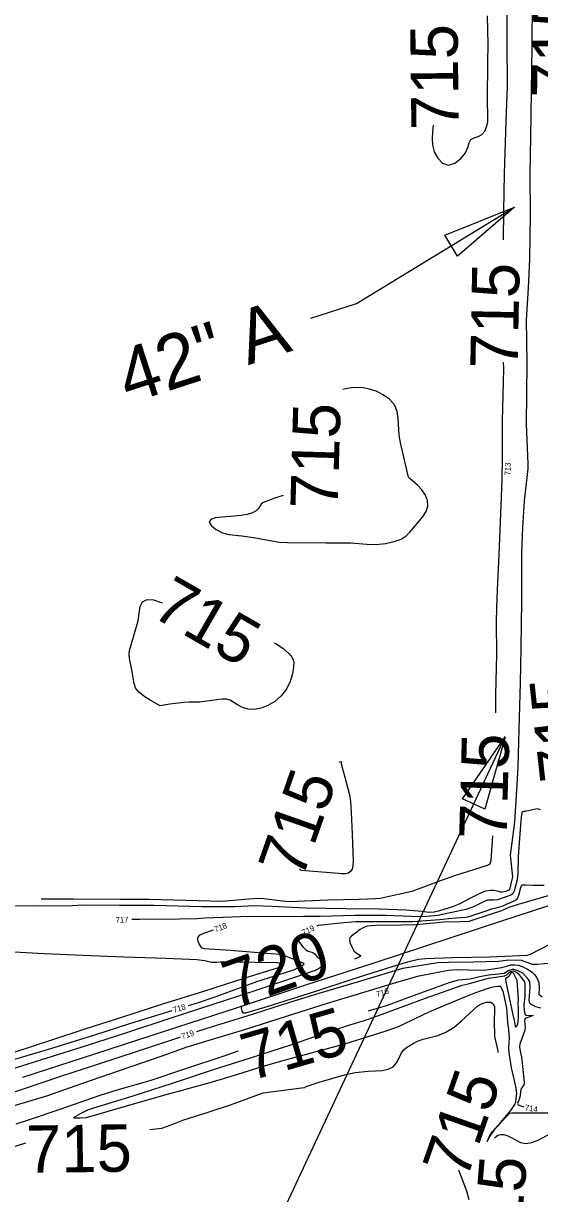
# Model space of a CAD drawing. Extents: x -468563856 to 36492962, y -306094093 to 11899197.
# Drawn here: x 1821405 to 1821764, y 530800 to 531615 of the extents above; entities that cross this region are included whole.
import ezdxf

# ---------------------------------------------------------------- set-up
doc = ezdxf.new("R2010")
doc.units = 0
for name, color, linetype in [('DT_X_Contour_Minor', 7, 'Continuous'), ('Level 14', 7, 'Continuous'), ('Level 19', 7, 'Continuous'), ('Level 40', 7, 'Continuous')]:
    doc.layers.add(name, color=color, linetype=linetype)

msp = doc.modelspace()

# ---------------------------------------------------------------- linework, layer by layer
at = {"layer": 'DT_X_Contour_Minor'}
for points in [[(1821388.03, 531000.73), (1821414.14, 531000.46), (1821438.84, 531000.74), (1821446.91, 531001.12), (1821471.57, 531001.1), (1821495.84, 531000.91), (1821528.89, 531000.07), (1821552.25, 530999.97), (1821565.46, 531000.79), (1821577.63, 531000.28), (1821601.34, 530999.03), (1821629.18, 530998.59), (1821652.32, 530998.42), (1821671.31, 530997.85), (1821682.44, 530996.77), (1821687.06, 530996.24), (1821690.73, 530996.39), (1821694.72, 530997.19), (1821704.38, 531000.36), (1821708.86, 531002.17), (1821716.6, 531006.24), (1821723.57, 531009.77), (1821726.71, 531010.86), (1821730.18, 531011.42), (1821732.15, 531011.43), (1821734.23, 531011.03), (1821736.8, 531010.2), (1821737.85, 531010.19), (1821740.72, 531010.85), (1821743.39, 531011.79), (1821745.56, 531020.63), (1821743.96, 531035.89), (1821746.8, 531058.75), (1821748.58, 531084.95), (1821749.12, 531097.03), (1821749.87, 531123.36), (1821750.84, 531155.7), (1821751.34, 531179.74), (1821751.76, 531212.69), (1821751.79, 531246.08), (1821752.49, 531263.83), (1821753.61, 531282.32), (1821755.13, 531296.61), (1821756.07, 531304.79), (1821756.14, 531307.91), (1821755.01, 531335.94), (1821755.13, 531356.71), (1821755.45, 531377.87), (1821755.06, 531408.36), (1821756.42, 531430.43), (1821757.25, 531450.55), (1821757.66, 531481.76), (1821757.58, 531509.72), (1821757.95, 531535.57), (1821758.5, 531567.06), (1821758.87, 531598.66), (1821759.23, 531630.84)], [(1821741.4, 531622.8), (1821741.18, 531602.32), (1821741.43, 531570.87), (1821740.66, 531546.47), (1821739.49, 531509.88), (1821738.91, 531484.16), (1821738.72, 531464.06)], [(1821690.01, 531543.78), (1821689.58, 531538.85), (1821689.38, 531534.49), (1821689.65, 531529.87), (1821690.81, 531525.17), (1821693.16, 531520.7), (1821696.55, 531517.32), (1821700.66, 531515.98), (1821705.15, 531517.29), (1821709.35, 531520.51), (1821712.51, 531524.5), (1821714.21, 531528.3), (1821715.15, 531531.49), (1821716.33, 531533.77), (1821718.49, 531535.04), (1821721.23, 531535.93), (1821723.88, 531537.24), (1821725.91, 531539.55), (1821727.24, 531542.56), (1821727.96, 531545.75), (1821728.15, 531548.79), (1821727.75, 531561.65), (1821728.14, 531587.49), (1821728.23, 531600.07), (1821727.94, 531619.84)], [(1821738.73, 531378.92), (1821738.93, 531374.69), (1821738.83, 531364.91), (1821738.01, 531338.1), (1821737.96, 531312.42), (1821737.74, 531297.08), (1821736.86, 531273.5), (1821735.81, 531244.88), (1821734.52, 531220.54), (1821734.01, 531208.13), (1821733.98, 531197.66), (1821734.14, 531175.73), (1821733.51, 531147.08), (1821733.42, 531134.72)], [(1821585.64, 531286.09), (1821579.66, 531284.23), (1821575.01, 531282.45), (1821572.89, 531281.73), (1821571.48, 531281.03), (1821570.23, 531279.99), (1821568.46, 531276.96), (1821566.88, 531275.37), (1821564.2, 531274), (1821560.57, 531272.93), (1821556.34, 531272.21), (1821538.34, 531270.63), (1821535.26, 531269.43), (1821534.18, 531267.57), (1821535.67, 531265.02), (1821539.07, 531262.33), (1821543.39, 531260.13), (1821547.85, 531258.9), (1821556.94, 531257.99), (1821566.26, 531256.72), (1821582.92, 531253.57), (1821588.63, 531253.35), (1821615.31, 531253.24), (1821632.67, 531253.08), (1821643.87, 531252.16), (1821650.36, 531252.08), (1821656.87, 531252.7), (1821662.84, 531253.96), (1821667.7, 531255.73), (1821671.12, 531257.91), (1821673.69, 531260.51), (1821682.62, 531270.93), (1821685.13, 531274.87), (1821686.3, 531278.75), (1821686.1, 531282.56), (1821684.64, 531286.3), (1821682.13, 531289.94), (1821679.19, 531293.17), (1821673.87, 531297.85), (1821672.95, 531298.91), (1821671.89, 531302.74), (1821667.33, 531322.83), (1821666.42, 531328.3), (1821665.81, 531335.42), (1821665.58, 531339.86), (1821664.85, 531344.56), (1821663.02, 531349.06), (1821659.66, 531352.99), (1821655.23, 531356.2), (1821650.42, 531358.61), (1821645.76, 531360.17), (1821641.34, 531360.98), (1821637.09, 531361.17), (1821633.02, 531360.9), (1821629.22, 531360.28), (1821627.12, 531359.72)], [(1821579.12, 531183.64), (1821580.61, 531183.05), (1821585.65, 531179.71), (1821589.56, 531176.23), (1821591.93, 531173.27), (1821592.93, 531170.38), (1821592.9, 531166.81), (1821592.09, 531162.05), (1821590.44, 531156.6), (1821587.81, 531151.24), (1821584.16, 531146.57), (1821579.77, 531142.78), (1821575.01, 531139.9), (1821570.21, 531137.98), (1821565.56, 531137.08), (1821561.19, 531137.27), (1821557.26, 531138.52), (1821553.84, 531140.36), (1821548.72, 531143.59), (1821546.28, 531144.36), (1821542.87, 531144.43), (1821532.42, 531142.98), (1821527.25, 531142.3), (1821519.85, 531142.2), (1821516.14, 531142.14), (1821506.81, 531140.92), (1821500.01, 531139.71), (1821493.11, 531143.63), (1821488.6, 531146.48), (1821484.81, 531149.47), (1821482.72, 531152.28), (1821481.85, 531155.25), (1821480.45, 531163.52), (1821478.61, 531172.62), (1821478.31, 531175.59), (1821478.64, 531178.17), (1821484.56, 531198.9), (1821486.15, 531209.05), (1821487.78, 531212.18), (1821490.93, 531213.62), (1821495.39, 531213.43), (1821500.78, 531211.69), (1821501.48, 531211.33)], [(1821624.55, 531100.61), (1821625.69, 531101), (1821626.1, 531100.67), (1821626.09, 531099.63), (1821626.28, 531098.36), (1821628.49, 531090.13), (1821631.76, 531077.76), (1821632.56, 531073.19), (1821632.92, 531065.69), (1821633.58, 531050.29), (1821634.39, 531031.65), (1821634.2, 531028.52), (1821633.59, 531026.1), (1821632.46, 531024.39), (1821630.93, 531023.31), (1821629.23, 531022.75), (1821626.03, 531022.69), (1821624.06, 531023), (1821598.2, 531025.11), (1821597.61, 531025.46), (1821597.3, 531026.21)], [(1821764.82, 531067.31), (1821762.32, 531067.94), (1821754.4, 531066.18), (1821752.95, 531066.15), (1821752.02, 531065.71), (1821751.46, 531064.41), (1821750.94, 531059.88), (1821749.1, 531034.83), (1821748.95, 531022.52), (1821748.16, 531017.72), (1821746.31, 531010.79), (1821745.46, 531008.92), (1821744.02, 531007.94), (1821734.79, 531004.82), (1821731.94, 531004.54), (1821727.68, 531004.5), (1821724.99, 531003.3), (1821718.05, 530999.95), (1821712.66, 530997.97), (1821693.18, 530993.78), (1821682.94, 530992.85), (1821674.88, 530993), (1821657.39, 530993.71), (1821635.62, 530993.92), (1821611.31, 530993.14), (1821599.8, 530993.19), (1821577.98, 530992.99), (1821573.8, 530993.12), (1821556.14, 530992.85), (1821531.03, 530991.97), (1821525.52, 530991.59), (1821513.51, 530991.3), (1821485.66, 530991.04), (1821480.23, 530990.94)], [(1821731.29, 531049.35), (1821730.07, 531032.1), (1821729.39, 531029.43), (1821727.72, 531028.6), (1821704.86, 531021.39), (1821697.06, 531018.66), (1821675.1, 531010.52), (1821653.12, 531005.67), (1821649.85, 531005.36), (1821638.2, 531004.98), (1821616.65, 531004.41), (1821589.93, 531003.22), (1821584.9, 531003.68), (1821572.11, 531005.38), (1821568.38, 531005.55), (1821561.62, 531005.17), (1821542.8, 531003.56), (1821526.53, 531004.06), (1821492.08, 531004.95), (1821472.54, 531004.95), (1821439.67, 531005.16), (1821417.17, 531005.06)], [(1821767.21, 531014.59), (1821759.94, 531014.74), (1821754.18, 531014.81), (1821751.81, 531014.86), (1821751.31, 531014.48), (1821750.87, 531012.97), (1821749.41, 531007.68), (1821748.66, 531005.91), (1821747.82, 531004.76), (1821745.61, 531003.54), (1821740.77, 531001.41), (1821737.7, 531000.02), (1821734.62, 530999.09), (1821730.73, 530998.2), (1821725.25, 530996.47), (1821716.31, 530993.26), (1821713.09, 530992.52), (1821706.1, 530991.96), (1821700.7, 530991.56), (1821694.61, 530990.76), (1821675.57, 530989.44), (1821671.96, 530989.37), (1821658.25, 530989.51), (1821635.99, 530989.39), (1821625.42, 530988.48), (1821610.06, 530986.84), (1821609.11, 530986.5)], [(1821772.38, 531008.25), (1821749.21, 531001.46), (1821742.69, 530999.26), (1821737.48, 530997.03), (1821735.44, 530996.26), (1821731.86, 530995.19), (1821714.81, 530989.63), (1821708.86, 530989.33), (1821697.44, 530989.2), (1821690.45, 530988.58), (1821678.27, 530987.3), (1821667.93, 530987.07), (1821649.85, 530986.92), (1821646.76, 530986.73), (1821644.12, 530986.29), (1821641.68, 530985.44), (1821639.25, 530984.07), (1821633.22, 530979.52), (1821632.11, 530978.28), (1821631.68, 530976.86), (1821631.97, 530975.09), (1821633.58, 530971.47), (1821634.89, 530969.25), (1821636.35, 530967.82), (1821639.34, 530966.05), (1821639.11, 530965.24), (1821636.44, 530963.84), (1821635.25, 530963.43)], [(1821556.93, 530931.18), (1821556.34, 530929.44), (1821556.77, 530927.2), (1821557.46, 530926.02), (1821559.59, 530926.08), (1821574.45, 530930.55), (1821608.44, 530941.22), (1821633.7, 530949.47), (1821661.44, 530958.4), (1821673.02, 530961.83), (1821679.91, 530963.4), (1821684.7, 530963.89), (1821703.51, 530964.55), (1821729.33, 530965.12), (1821755.5, 530966.09), (1821757.73, 530967.01), (1821771.63, 530974.15), (1821773.55, 530975.78), (1821774.46, 530977.69), (1821775.14, 530982.55), (1821776.5, 530985.4), (1821777, 530986.98), (1821776.97, 530989.17), (1821776.97, 530989.24)], [(1821598.48, 530980.92), (1821597.11, 530980.08), (1821596.07, 530978.87), (1821595.93, 530977.51), (1821596.62, 530975.8), (1821599.12, 530972.26), (1821601.15, 530970.07), (1821603.11, 530969.05), (1821606.34, 530967.97), (1821607.88, 530966.95), (1821609.32, 530965.16), (1821611.87, 530962.82), (1821612.85, 530961.42), (1821613.08, 530960.02), (1821612.62, 530958.7), (1821611.64, 530957.55), (1821610.23, 530956.61), (1821607.96, 530955.63), (1821592.8, 530950.44), (1821564.4, 530940.99), (1821536.01, 530931.66), (1821506.6, 530922.07), (1821477.15, 530912.37), (1821449.2, 530903.38), (1821421.18, 530894.46), (1821390.9, 530884.92)], [(1821519.75, 530931.18), (1821525.88, 530933), (1821538.2, 530937.17), (1821567.32, 530947.92), (1821593.07, 530956.08), (1821598.11, 530958.47), (1821600.23, 530959.82), (1821599.91, 530960.31), (1821594.91, 530962.52), (1821584.49, 530966.61), (1821576.77, 530967.09), (1821549.01, 530969.47), (1821530.82, 530970.62), (1821529.18, 530971.15), (1821528.28, 530972.25), (1821527.16, 530974.13), (1821526.24, 530976.43), (1821526.27, 530978.6), (1821527.78, 530980.27), (1821530.4, 530981.51), (1821537.13, 530983.83)], [(1821389.97, 530969.09), (1821419.18, 530967.44), (1821446.38, 530966.11), (1821474.63, 530965.13), (1821504.1, 530964.1), (1821525.48, 530963.28), (1821531.19, 530962.38), (1821535.72, 530961.42), (1821539.52, 530961.38), (1821541.81, 530961.63), (1821557.41, 530961.59), (1821574.35, 530961.2), (1821580.23, 530961.27), (1821583.7, 530960.65), (1821585.73, 530959.61), (1821585.75, 530959.19), (1821584.62, 530958.54), (1821582.15, 530957.5), (1821558.96, 530950.14), (1821530.04, 530940.88), (1821501.71, 530932.02), (1821472.96, 530922.85), (1821448.26, 530915.06), (1821424.26, 530907.13), (1821398.74, 530898.66)], [(1821525.61, 530913.05), (1821536.33, 530916.51), (1821560.44, 530924.1), (1821589.51, 530933.21), (1821610.74, 530939.68), (1821641.28, 530948.87), (1821668.96, 530957.14), (1821687.52, 530960.17), (1821693.34, 530961.03), (1821700.64, 530961.39), (1821718.09, 530961.61), (1821735.5, 530962.14), (1821740.94, 530962.65), (1821742.65, 530963), (1821751.36, 530962.68), (1821753.21, 530962.09), (1821759.1, 530959.83), (1821762.67, 530960), (1821777.19, 530961.33), (1821778.48, 530961.47)], [(1821771.63, 530856.23), (1821744.83, 530856.35), (1821743.17, 530855.93), (1821740.18, 530852.9), (1821732.08, 530843.89), (1821729.42, 530840.2), (1821727.62, 530836.54), (1821729.73, 530841.18), (1821731.36, 530843.57), (1821737.25, 530850.31), (1821744.09, 530858.22), (1821746.91, 530862.36), (1821747.67, 530864.05), (1821747.84, 530866.41), (1821748.2, 530869.92), (1821747.89, 530873.43), (1821746.67, 530879.01), (1821744.61, 530887.81), (1821742.88, 530898.48), (1821742.73, 530901.43), (1821743.19, 530908.81), (1821742.69, 530914.05), (1821742.04, 530919.91), (1821741.27, 530929.32), (1821738.89, 530940.16), (1821737.36, 530943.87), (1821736.83, 530944.3), (1821735.11, 530944.46), (1821731.65, 530943.84), (1821728.06, 530942.95), (1821719.44, 530939.96), (1821712.62, 530937.17), (1821699.18, 530931.59), (1821687.57, 530926.77), (1821665.73, 530916.31), (1821656.45, 530913.09), (1821628.21, 530904.36), (1821610.28, 530899.38), (1821584.4, 530892.56), (1821570.78, 530888.55), (1821553.81, 530883.27), (1821534.64, 530877.46), (1821504.88, 530869.27), (1821482.75, 530862.93), (1821448.47, 530853.01), (1821444.21, 530852.74), (1821440.25, 530852.7), (1821439.67, 530852.95), (1821440.11, 530853.43), (1821444.97, 530856.31), (1821449.74, 530858.58), (1821453.77, 530859.9), (1821481.14, 530868.43), (1821508.53, 530877.09), (1821537.2, 530886.55), (1821562.83, 530894.76), (1821591.57, 530903.98), (1821613.71, 530911.66), (1821632.03, 530917.67), (1821642.27, 530920.73), (1821654.53, 530925.11), (1821684.73, 530936.3), (1821710.1, 530945.4), (1821714.38, 530946.21), (1821728.42, 530950.19), (1821735.06, 530951.18), (1821739.68, 530951.86), (1821741.25, 530952.47), (1821741.97, 530953.26), (1821742.81, 530954.19), (1821744.21, 530954.99), (1821745.68, 530955.19), (1821747.53, 530954.58), (1821749.26, 530953.5), (1821749.98, 530952.46), (1821751.32, 530950.6), (1821753.68, 530947.54), (1821753.88, 530945.81), (1821753.82, 530937.38), (1821753.1, 530931.72), (1821753.45, 530927.36), (1821754.01, 530924.86), (1821754.5, 530924.52), (1821759.53, 530924.27), (1821754.14, 530922.06), (1821753.67, 530921.07), (1821753.84, 530918.18), (1821753.98, 530916.22), (1821753.76, 530913.94), (1821752.99, 530911.38), (1821750.36, 530904.2), (1821750.13, 530902.44)], [(1821472.3, 530886.16), (1821501.34, 530896.27), (1821518.74, 530902.36), (1821536.41, 530907.77), (1821559.55, 530914.72), (1821588, 530923.71), (1821616.46, 530932.78), (1821645.76, 530941.65), (1821664.8, 530947.5), (1821680.31, 530951.73), (1821689.75, 530953.71), (1821700.68, 530955.76), (1821705.93, 530956.24), (1821714.63, 530956.02), (1821724.99, 530955.88), (1821730.27, 530956.39), (1821737.71, 530957.61), (1821741.15, 530958.55), (1821743.89, 530959.48), (1821746.81, 530959.59), (1821749.11, 530959.31), (1821752.45, 530958.03), (1821755.79, 530956.48), (1821758.94, 530954.33), (1821760.46, 530952.78), (1821762.07, 530950.47), (1821762.88, 530948.9), (1821763.47, 530947.09), (1821763.69, 530943.26), (1821763.49, 530939.01), (1821765.91, 530937.15)], [(1821764.98, 530929.42), (1821761.56, 530930.34), (1821758.16, 530931.77), (1821757.48, 530932.34), (1821757.02, 530933.4), (1821756.95, 530935.06), (1821757.56, 530943.39), (1821757.33, 530947.79), (1821756.3, 530949.22), (1821752.35, 530953.67), (1821749.02, 530955.41), (1821746.17, 530956.34), (1821745.01, 530956.33), (1821742.79, 530955.51), (1821739.42, 530953.53), (1821728.66, 530952.21), (1821722.23, 530951.11), (1821715.77, 530949.6), (1821707.72, 530948.85), (1821701.62, 530947.11), (1821681.31, 530939.72), (1821657.24, 530931.06), (1821644.87, 530927.3)], [(1821740.31, 530948.72), (1821745.54, 530924.75), (1821746.52, 530919.86), (1821747.16, 530916.6), (1821747.56, 530916.15), (1821748.06, 530916.46), (1821748.93, 530918.2), (1821749.07, 530919.83), (1821749.35, 530923.46), (1821749.39, 530929.2), (1821749.27, 530932.89), (1821749.38, 530935.46), (1821748.46, 530948.57), (1821746.05, 530953.74), (1821744.84, 530954.03), (1821744.17, 530953.77), (1821743.6, 530953.07), (1821742.78, 530951.32), (1821740.45, 530949.75), (1821740.31, 530948.72)], [(1821492.9, 530844.86), (1821501.11, 530845.76), (1821507.64, 530848.25), (1821515.76, 530851.33), (1821534.14, 530857.12), (1821548.99, 530862.09), (1821571.73, 530870.42), (1821598.27, 530873.9), (1821600.79, 530874.23), (1821601.1, 530874.47), (1821602.27, 530875.03), (1821610.6, 530877.81), (1821628.21, 530882.97), (1821635.78, 530884.48), (1821644.84, 530885.39), (1821654.44, 530886.03), (1821658.67, 530886.78), (1821662.13, 530888.49), (1821664.64, 530891.44), (1821668.06, 530898.17), (1821669.71, 530900.39), (1821671.56, 530901.89), (1821676.16, 530904.7), (1821679.2, 530906.28), (1821683.03, 530907.7), (1821693.19, 530910.3), (1821698.9, 530912.62), (1821704.57, 530916.21), (1821709.85, 530920.52), (1821721.19, 530930.92), (1821724.11, 530932.66), (1821727.14, 530933.49), (1821729.9, 530933.39), (1821731.87, 530932.31), (1821732.69, 530930.27), (1821732.72, 530927.49), (1821732.44, 530920.84), (1821732.74, 530909.69), (1821734.95, 530899.53), (1821735.03, 530898.48)], [(1821392.62, 530892), (1821423.93, 530901.3), (1821454.46, 530910.83), (1821478.96, 530918.63), (1821506.03, 530927.1), (1821508.25, 530927.76)], [(1821251.22, 530820.8), (1821263.56, 530824.25), (1821265.44, 530824.75), (1821277.23, 530829.55), (1821294.11, 530835.98), (1821306.1, 530840.14), (1821334.35, 530849.22), (1821354.52, 530856.11), (1821381.43, 530865.42), (1821404.23, 530873.06), (1821430.88, 530882.06), (1821456.62, 530890.46), (1821484.17, 530899.5), (1821512.94, 530908.96), (1821514.19, 530909.36)], [(1821554.36, 530899.34), (1821544.38, 530895.98), (1821516.24, 530886.7), (1821492.78, 530878.74), (1821482.04, 530875.71), (1821471.34, 530872.74), (1821457.97, 530868.47), (1821430.24, 530858.74), (1821408.71, 530851.67), (1821399.56, 530848.65)], [(1821750.13, 530902.44), (1821750.51, 530899.5), (1821751.54, 530895.25), (1821753.17, 530880.3), (1821753.41, 530877.35), (1821753.18, 530876.07), (1821751.93, 530874.24), (1821751.32, 530873.39), (1821750.84, 530871.27), (1821750.54, 530868.28), (1821749.61, 530865.26), (1821748.62, 530863.05), (1821749.26, 530862.11), (1821751.82, 530861.02), (1821753.18, 530860.69)], [(1821393.07, 530860.01), (1821421.74, 530868.63), (1821444.68, 530876.69), (1821472.3, 530886.16)], [(1821732.67, 530838.9), (1821733.58, 530839.89), (1821734.94, 530840.87), (1821736.82, 530841.48), (1821739.21, 530841.37), (1821741.95, 530840.56), (1821744.85, 530839.18), (1821747.75, 530837.42), (1821750.87, 530835.87), (1821754.45, 530835.21), (1821758.69, 530835.93), (1821763.47, 530837.8), (1821773.77, 530843.23)], [(1821396.23, 530832.35), (1821406.47, 530835.68)], [(1821707.66, 530816.88), (1821708.32, 530815.04), (1821713.19, 530802.21), (1821714.82, 530796.11)]]:
    msp.add_lwpolyline(points, dxfattribs=at)
at = {"layer": 'Level 14'}
msp.add_lwpolyline([(1822444.29, 531219.73), (1822402.07, 531205.86), (1822362.27, 531192.96), (1822315.04, 531177.42), (1822270.18, 531162.88), (1822228.03, 531149.28), (1822183.88, 531134.78), (1822142.19, 531121.34), (1822099.37, 531107.28), (1822054.26, 531092.67), (1822008.51, 531077.84), (1821962.66, 531063), (1821916.5, 531048.08), (1821870, 531032.72), (1821825.04, 531018.18), (1821780.22, 531003.71), (1821737.66, 530989.77), (1821648.73, 530960.74), (1821601.95, 530945.47), (1821553.57, 530929.66), (1821503.52, 530913.42), (1821454.26, 530897.29), (1821404.04, 530881.11)], dxfattribs=at)
at = {"layer": 'Level 40'}
for p, q in [((1821636.54, 531419.64), (1821746.57, 531486.78)), ((1821698.06, 531467.25), (1821746.57, 531486.78)), ((1821746.57, 531486.78), (1821707.01, 531452.59)), ((1821707.01, 531452.59), (1821698.06, 531467.25)), ((1821604.93, 531409.37), (1821636.54, 531419.64)), ((1821466.95, 530534.8), (1821740.2, 531118.06)), ((1821710.53, 531075), (1821740.2, 531118.06)), ((1821740.2, 531118.06), (1821726.08, 531067.71)), ((1821726.08, 531067.71), (1821710.53, 531075))]:
    msp.add_line(p, q, dxfattribs=at)

# ---------------------------------------------------------------- texts
at = {"layer": 'Level 19'}
for s, height, rotation, p in [('715', 33, 89.60487, (1821791.78, 531562.77)), ('715', 33, 90.65338, (1821707.86, 531540.58)), ('715', 33, 88.91732, (1821748.83, 531374.1)), ('715', 33, 88.38447, (1821623.55, 531276.42)), ('713', 4, 89.03764, (1821743.83, 531300.02)), ('715', 33, 330.02369, (1821492.79, 531202.77)), ('715', 33, 96.34285, (1821797.58, 531088.97)), ('715', 33, 88.46468, (1821741.07, 531046.43)), ('715', 33, 70.61705, (1821598.69, 531018.15)), ('717', 4, 1.04278, (1821469.01, 530988.73)), ('718', 4, 20.5921, (1821538.59, 530982.09)), ('719', 4, 26.88318, (1821599.89, 530979.78)), ('720', 33, 19.38889, (1821551.09, 530928.89)), ('716', 4, 17.7445, (1821651.08, 530936.88)), ('718', 4, 16.56421, (1821509.55, 530926.06)), ('715', 33, 16.15741, (1821562.35, 530878.52)), ('719', 4, 17.91066, (1821515.51, 530907.68)), ('715', 33, 70.66091, (1821713.12, 530809.09)), ('714', 4, 350.10586, (1821753.57, 530858.35)), ('715', 33, 0.77922, (1821406.8, 530814.63)), ('715', 33, 85.18736, (1821749.29, 530751.55))]:
    msp.add_text(s, height=height, rotation=rotation, dxfattribs=at).set_placement(p)
at = {"layer": 'Level 40'}
msp.add_text('42" A', height=37.5, rotation=17.9864, dxfattribs=at).set_placement((1821477.88, 531349.67))

doc.saveas('drawing.dxf')
